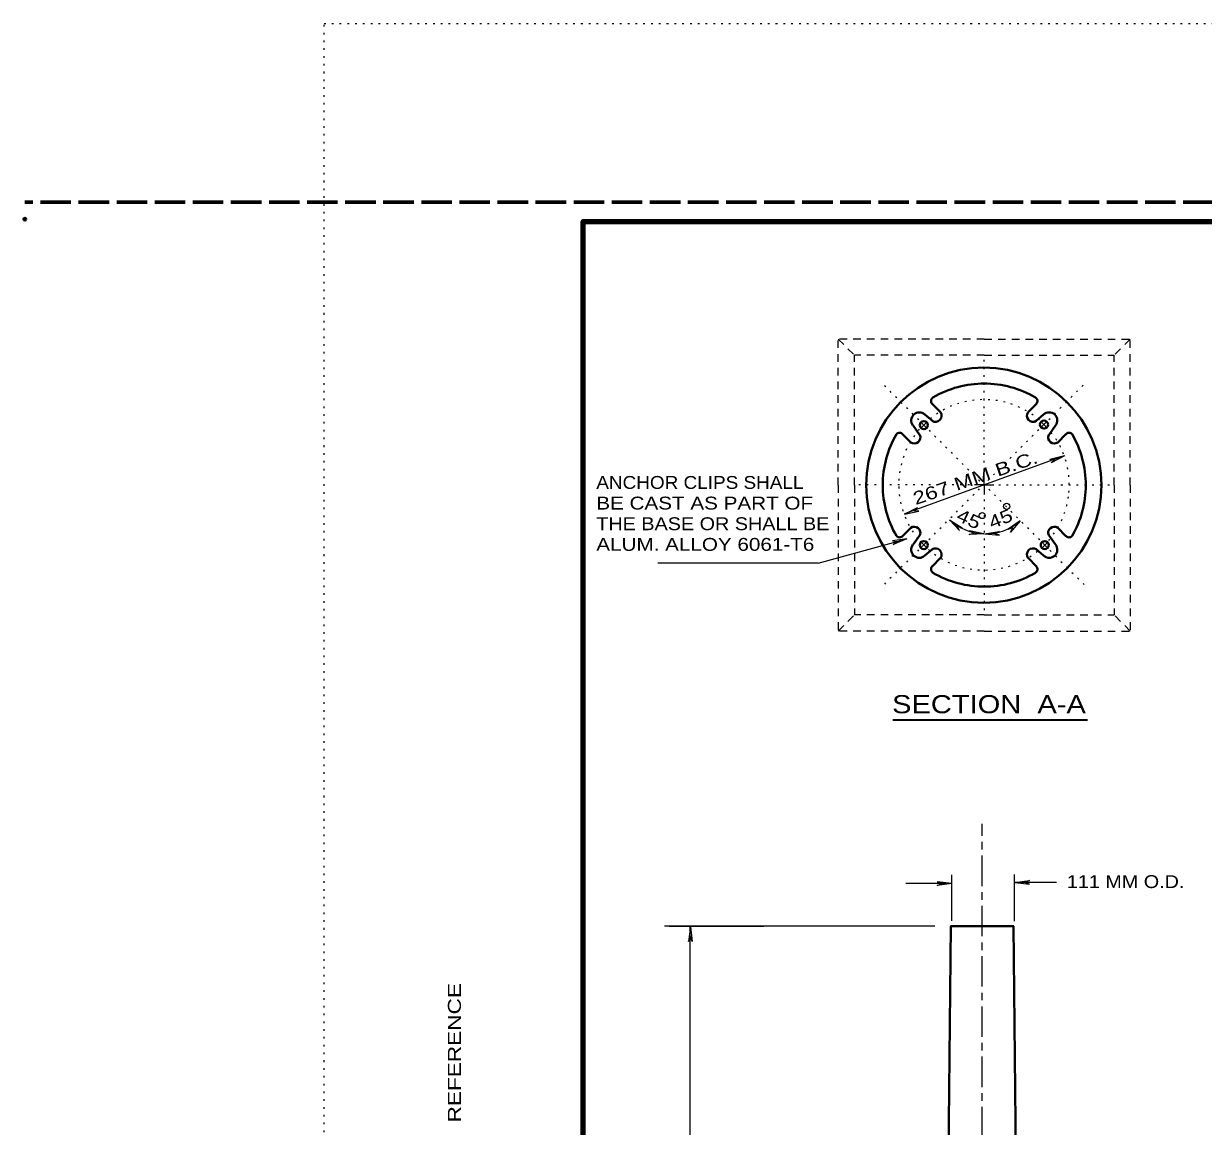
# Model space of a CAD drawing. Extents: x 312583 to 312854, y 144419 to 144597.
# Drawn here: x 312583.5 to 312653.1, y 144531.6 to 144596.8 of the extents above; entities that cross this region are included whole.
import ezdxf
from ezdxf.enums import TextEntityAlignment as Align

# ---------------------------------------------------------------- set-up
doc = ezdxf.new("R2010")
doc.units = 0
doc.header["$LTSCALE"] = 0.3
doc.header["$PDMODE"] = 32
doc.header["$PDSIZE"] = 0.15
for name, pattern in [('DOTTED', [1.5, 0.3, -1.2]), ('LONG_DASH_SHORT_DASH', [9.9, 6, -1.2, 1.5, -1.2]), ('LONG_DASHED', [7.5, 6, -1.5]), ('SHORT_DASHED', [2.7, 1.5, -1.2])]:
    doc.linetypes.add(name, pattern=pattern)
for name, color, linetype, lineweight in [('1', 7, 'Continuous', 40), ('2', 7, 'Continuous', 13), ('62', 7, 'DOTTED', 13), ('63', 7, 'LONG_DASHED', 60)]:
    doc.layers.add(name, color=color, linetype=linetype, lineweight=lineweight)

msp = doc.modelspace()

# ---------------------------------------------------------------- linework, layer by layer
at = {"layer": '1', "linetype": 'SHORT_DASHED', "lineweight": 25}
for p, q in [((312631.5804, 144578.1416), (312632.5387, 144577.1833)), ((312640.2054, 144578.1416), (312631.5804, 144578.1416)), ((312631.5804, 144569.5166), (312631.5804, 144578.1416)), ((312640.2054, 144578.1416), (312648.8304, 144578.1416)), ((312648.8304, 144578.1416), (312647.872, 144577.1833)), ((312648.8304, 144569.5166), (312648.8304, 144578.1416)), ((312640.2054, 144577.1833), (312632.5387, 144577.1833)), ((312632.5387, 144569.5166), (312632.5387, 144577.1833)), ((312640.2054, 144577.1833), (312647.872, 144577.1833)), ((312647.872, 144569.5166), (312647.872, 144577.1833)), ((312631.5804, 144569.5166), (312631.5804, 144560.8916)), ((312632.5387, 144569.5166), (312632.5387, 144561.8499)), ((312647.872, 144569.5166), (312647.872, 144561.8499)), ((312648.8304, 144569.5166), (312648.8304, 144560.8916)), ((312631.5804, 144560.8916), (312632.5387, 144561.8499)), ((312640.2054, 144561.8499), (312632.5387, 144561.8499)), ((312640.2054, 144561.8499), (312647.872, 144561.8499)), ((312648.8304, 144560.8916), (312647.872, 144561.8499)), ((312640.2054, 144560.8916), (312631.5804, 144560.8916)), ((312640.2054, 144560.8916), (312648.8304, 144560.8916))]:
    msp.add_line(p, q, dxfattribs=at)
at = {"layer": '1'}
for p, q in [((312637.614, 144573.8253), (312637.1234, 144574.3236)), ((312642.7967, 144573.8253), (312643.2797, 144574.3236)), ((312636.694, 144573.6873), (312637.1387, 144573.3039)), ((312643.709, 144573.6873), (312643.272, 144573.3039)), ((312635.9964, 144573.0356), (312636.4027, 144572.4683)), ((312644.4144, 144573.0356), (312644.008, 144572.4683)), ((312635.8584, 144572.0389), (312635.3754, 144572.5219)), ((312644.5447, 144572.0389), (312645.0277, 144572.5219)), ((312635.8584, 144566.9866), (312635.3754, 144566.5036)), ((312635.9964, 144565.9976), (312636.4027, 144566.5573)), ((312644.4144, 144565.9976), (312644.008, 144566.5573)), ((312644.5447, 144566.9866), (312645.0277, 144566.5036)), ((312636.694, 144565.3459), (312637.1387, 144565.7293)), ((312643.709, 144565.3459), (312643.272, 144565.7293)), ((312637.614, 144565.2079), (312637.1234, 144564.7096)), ((312642.7967, 144565.2079), (312643.2797, 144564.7096)), ((312638.2185, 144543.4576), (312637.4058, 144462.9576)), ((312640.0738, 144543.4576), (312638.2032, 144543.4576)), ((312640.0738, 144543.4576), (312638.2032, 144543.4576)), ((312640.0738, 144543.4576), (312638.2032, 144543.4576)), ((312640.0738, 144543.4576), (312638.2032, 144543.4576)), ((312640.0738, 144543.4576), (312638.2032, 144543.4576)), ((312640.0738, 144543.4576), (312638.2185, 144543.4576)), ((312640.0738, 144543.4576), (312638.2185, 144543.4576)), ((312640.0738, 144543.4576), (312638.2185, 144543.4576)), ((312640.0738, 144543.4576), (312641.9292, 144543.4576)), ((312640.0738, 144543.4576), (312641.9292, 144543.4576)), ((312640.0738, 144543.4576), (312641.9522, 144543.4576)), ((312640.0738, 144543.4576), (312641.9598, 144543.4576)), ((312640.0738, 144543.4576), (312641.9598, 144543.4576)), ((312640.0738, 144543.4576), (312641.9598, 144543.4576)), ((312640.0738, 144543.4576), (312641.9598, 144543.4576)), ((312640.0738, 144543.4576), (312641.9598, 144543.4576)), ((312641.9292, 144543.4576), (312642.7495, 144463.0189))]:
    msp.add_line(p, q, dxfattribs=at)
at = {"layer": '1', "linetype": 'LONG_DASH_SHORT_DASH', "lineweight": 13}
msp.add_line((312640.0738, 144435.9326), (312640.0738, 144549.4913), dxfattribs=at)
at = {"layer": '1', "lineweight": 158}
msp.add_lwpolyline([(312616.5, 144423.1446), (312616.5, 144585.0846), (312849, 144585.0846)], dxfattribs=at)
at = {"layer": '1'}
for centre, radius in [((312640.1766, 144569.5089), 6.9479), ((312636.6317, 144573.0586), 0.2396), ((312643.733, 144573.0902), 0.2396), ((312636.6315, 144565.9707), 0.2396), ((312643.7752, 144565.9708), 0.2396)]:
    msp.add_circle(centre, radius, dxfattribs=at)
for centre, radius, start, end in [((312640.1977, 144569.5233), 5.9896, 89.72496, 120.33706), ((312640.2092, 144569.5233), 5.9896, 59.66294, 90.27504), ((312637.2978, 144574.4836), 0.2396, 121.00239, 225), ((312643.1091, 144574.4836), 0.2396, 315, 58.99761), ((312636.3672, 144573.3336), 0.4792, 46.88819, 218.60629), ((312637.3246, 144573.6096), 0.3594, 236.98896, 36.62133), ((312643.0823, 144573.6096), 0.3594, 143.37867, 303.01104), ((312644.0397, 144573.3336), 0.4792, 321.39371, 133.11181), ((312640.1977, 144569.5233), 5.9896, 150.02049, 180.0825), ((312635.1952, 144572.3657), 0.2396, 36.37482, 139.39871), ((312636.0692, 144572.3322), 0.3594, 234.40922, 24.08745), ((312644.3377, 144572.3322), 0.3594, 155.91255, 305.59078), ((312645.2117, 144572.3657), 0.2396, 40.60129, 143.62518), ((312640.2092, 144569.5233), 5.9896, 359.9175, 29.97951), ((312640.1977, 144569.5061), 5.9896, 179.9175, 209.97951), ((312640.2092, 144569.5061), 5.9896, 330.02049, 0.0825), ((312635.1952, 144566.6636), 0.2396, 220.60129, 323.62518), ((312636.0692, 144566.6972), 0.3594, 335.91255, 125.59078), ((312644.3377, 144566.6972), 0.3594, 54.40922, 204.08745), ((312645.2117, 144566.6636), 0.2396, 216.37482, 319.39871), ((312636.3672, 144565.6957), 0.4792, 141.39371, 313.11181), ((312637.3246, 144565.4197), 0.3594, 323.37867, 123.01104), ((312643.0823, 144565.4197), 0.3594, 56.98896, 216.62133), ((312644.0397, 144565.6957), 0.4792, 226.88819, 38.60629), ((312637.2978, 144564.5457), 0.2396, 135, 238.99761), ((312640.1977, 144569.5061), 5.9896, 239.66294, 270.27504), ((312640.2092, 144569.5061), 5.9896, 269.72496, 300.33706), ((312643.1091, 144564.5457), 0.2396, 301.00239, 45)]:
    msp.add_arc(centre, radius, start, end, dxfattribs=at)
at = {"layer": '1', "linetype": 'DOTTED', "lineweight": 13}
for start, end in [(49.54411, 130.96329), (139.37506, 221.06538), (354.93337, 40.82108), (319.35508, 355.03073), (229.27706, 310.97044)]:
    msp.add_arc((312640.1872, 144569.53), 5.0399, start, end, dxfattribs=at)
at = {"layer": '1'}
msp.add_point((312583.526, 144585.2246), dxfattribs=at)
at = {"layer": '2', "linetype": 'DOTTED'}
for p, q in [((312640.1977, 144570.3829), (312640.1977, 144577.0606)), ((312636.3337, 144573.3653), (312634.302, 144575.3969)), ((312644.0234, 144573.3883), (312646.055, 144575.4276)), ((312636.9394, 144572.7519), (312640.1747, 144569.5166)), ((312643.4177, 144572.7826), (312640.167, 144569.5396)), ((312639.3314, 144569.5243), (312632.738, 144569.5243)), ((312636.9317, 144566.2966), (312640.167, 144569.5319)), ((312643.479, 144566.2736), (312640.2207, 144569.5243)), ((312641.0564, 144569.5243), (312647.7264, 144569.5243)), ((312640.1977, 144568.6579), (312640.1977, 144561.9803)), ((312636.326, 144565.6833), (312634.2867, 144563.6516)), ((312644.0847, 144565.6603), (312646.1164, 144563.6286))]:
    msp.add_line(p, q, dxfattribs=at)
at = {"layer": '2'}
for p, q in [((312636.6404, 144573.0586), (312636.4334, 144573.2579)), ((312636.6404, 144573.0586), (312636.4334, 144572.8516)), ((312636.6404, 144573.0586), (312636.8397, 144573.2579)), ((312636.6404, 144573.0586), (312636.8397, 144572.8516)), ((312643.7167, 144573.0893), (312643.5174, 144573.2886)), ((312643.7167, 144573.0893), (312643.5174, 144572.8823)), ((312643.7167, 144573.0893), (312643.9237, 144573.2886)), ((312643.7167, 144573.0893), (312643.9237, 144572.8823)), ((312644.928, 144571.2493), (312635.4827, 144567.8069)), ((312644.9357, 144571.2339), (312644.0847, 144571.0346)), ((312644.0847, 144571.0346), (312644.376, 144571.0269)), ((312644.9357, 144571.2339), (312644.1537, 144570.8353)), ((312644.1537, 144570.8353), (312644.376, 144571.0269)), ((312640.1977, 144569.5243), (312640.1977, 144570.0993)), ((312640.1977, 144569.5243), (312639.6227, 144569.5243)), ((312640.1594, 144569.5013), (312640.19, 144569.4706)), ((312640.1977, 144569.5243), (312640.7727, 144569.5243)), ((312640.1977, 144569.5243), (312640.1977, 144568.9493)), ((312636.1497, 144568.0523), (312635.4827, 144567.8069)), ((312635.4904, 144567.7916), (312636.2647, 144568.1903)), ((312635.4904, 144567.7916), (312636.3414, 144567.9833)), ((312636.2647, 144568.1903), (312636.0424, 144567.9909)), ((312636.3414, 144567.9833), (312636.0424, 144567.9909)), ((312638.1584, 144567.4696), (312638.7487, 144566.8333)), ((312638.1584, 144567.4696), (312638.8944, 144566.9943)), ((312642.329, 144567.4006), (312641.616, 144566.9023)), ((312642.329, 144567.4006), (312641.754, 144566.7413)), ((312638.7487, 144566.8333), (312638.6107, 144567.0863)), ((312638.8944, 144566.9943), (312638.6107, 144567.0863)), ((312639.3084, 144566.5956), (312639.592, 144566.6799)), ((312640.1824, 144566.6339), (312639.3084, 144566.5956)), ((312639.3237, 144566.8103), (312639.592, 144566.6799)), ((312640.1824, 144566.6339), (312639.3237, 144566.8103)), ((312640.2207, 144566.6339), (312641.087, 144566.7643)), ((312640.2207, 144566.6339), (312641.0947, 144566.5496)), ((312641.087, 144566.7643), (312640.811, 144566.6493)), ((312641.0947, 144566.5496), (312640.811, 144566.6493)), ((312641.616, 144566.9023), (312641.892, 144567.0096)), ((312641.754, 144566.7413), (312641.892, 144567.0096)), ((312630.392, 144564.9013), (312635.636, 144566.3349)), ((312635.636, 144566.3349), (312634.7774, 144566.2123)), ((312634.7774, 144566.2123), (312635.0687, 144566.1816)), ((312635.636, 144566.3349), (312634.831, 144566.0053)), ((312634.831, 144566.0053), (312635.0687, 144566.1816)), ((312636.625, 144565.9899), (312636.4257, 144566.1969)), ((312636.625, 144565.9899), (312636.4257, 144565.7906)), ((312636.625, 144565.9899), (312636.832, 144566.1969)), ((312636.625, 144565.9899), (312636.832, 144565.7906)), ((312643.778, 144565.9669), (312643.5787, 144566.1739)), ((312643.778, 144565.9669), (312643.5787, 144565.7676)), ((312643.778, 144565.9669), (312643.985, 144566.1663)), ((312643.778, 144565.9669), (312643.9927, 144565.7599)), ((312630.392, 144564.9013), (312620.9125, 144564.9013)), ((312638.2875, 144543.7643), (312638.2875, 144546.4859)), ((312641.9828, 144543.7413), (312641.9828, 144546.5013)), ((312638.2798, 144545.9646), (312635.5658, 144545.9646)), ((312637.4135, 144546.0719), (312637.6895, 144545.9646)), ((312638.2798, 144545.9646), (312637.4135, 144546.0719)), ((312637.4135, 144545.8573), (312637.6895, 144545.9646)), ((312638.2798, 144545.9646), (312637.4135, 144545.8573)), ((312642.0135, 144546.0413), (312642.8798, 144546.1486)), ((312644.4745, 144546.0413), (312642.0135, 144546.0413)), ((312642.0135, 144546.0413), (312642.8798, 144545.9339)), ((312642.8798, 144546.1486), (312642.6038, 144546.0413)), ((312642.8798, 144545.9339), (312642.6038, 144546.0413)), ((312624.8632, 144543.4423), (312621.3098, 144543.4423)), ((312627.1785, 144543.4269), (312621.5864, 144543.4269)), ((312622.8453, 144543.4193), (312622.738, 144542.5529)), ((312622.8453, 144543.4193), (312622.8147, 144543.1969)), ((312622.8377, 144451.5266), (312622.8377, 144543.4269)), ((312622.8453, 144543.4193), (312622.8683, 144543.1969)), ((312622.8453, 144543.4193), (312622.9527, 144542.5529)), ((312637.2908, 144543.4423), (312624.8632, 144543.4423)), ((312622.738, 144542.5529), (312622.8453, 144542.8289)), ((312622.8147, 144543.1969), (312622.8453, 144543.2659)), ((312622.8683, 144543.1969), (312622.8453, 144543.2659)), ((312622.9527, 144542.5529), (312622.8453, 144542.8289))]:
    msp.add_line(p, q, dxfattribs=at)
at = {"layer": '2', "lineweight": 35}
msp.add_line((312646.2989, 144555.6207), (312634.8007, 144555.6207), dxfattribs=at)
at = {"layer": '2'}
for centre in [(312640.0806, 144567.7149), (312641.5286, 144568.2582)]:
    msp.add_circle(centre, 0.1797, dxfattribs=at)
for start, end in [(226.93367, 268.11084), (268.9061, 311.17586)]:
    msp.add_arc((312640.282, 144569.7409), 3.1095, start, end, dxfattribs=at)
at = {"layer": '62'}
for p, q in [((312601.2, 144596.7846), (312853.5, 144596.7846)), ((312601.2, 144418.5846), (312601.2, 144596.7846))]:
    msp.add_line(p, q, dxfattribs=at)
at = {"layer": '63'}
msp.add_line((312851.75, 144586.2246), (312583.526, 144586.2246), dxfattribs=at)

# ---------------------------------------------------------------- texts
at = {"layer": '1', "width": 1.3}
msp.add_text('REFERENCE                                                              ', height=0.7682, rotation=90, dxfattribs=at).set_placement((312609.2854, 144531.8549))
at = {"layer": '2'}
for s, rotation, width, p in [('267 MM B.C.', 19, 1.3, (312636.1487, 144568.3303)), ('45', 336, 1.25, (312638.4958, 144567.4508)), ('45', 22, 1.25, (312640.6511, 144566.9077))]:
    msp.add_text(s, height=0.76, rotation=rotation, dxfattribs=dict(at, width=width)).set_placement(p)
for s, width, p in [('ANCHOR CLIPS SHALL', 1.1, (312617.2837, 144569.2913)), ('BE CAST AS PART OF', 1.2, (312617.2837, 144568.0713)), ('THE BASE OR SHALL BE', 1.15, (312617.2837, 144566.8513)), ('ALUM. ALLOY 6061-T6', 1.2, (312617.2837, 144565.6313)), ('111 MM O.D.', 1.15, (312645.0791, 144545.7048))]:
    msp.add_text(s, height=0.76, dxfattribs=dict(at, width=width)).set_placement(p)
at = {"layer": '2', "width": 1.2}
msp.add_text('SECTION  A-A', height=1.07, dxfattribs=at).set_placement((312640.4817, 144556.0333), align=Align.CENTER)

doc.saveas('drawing.dxf')
